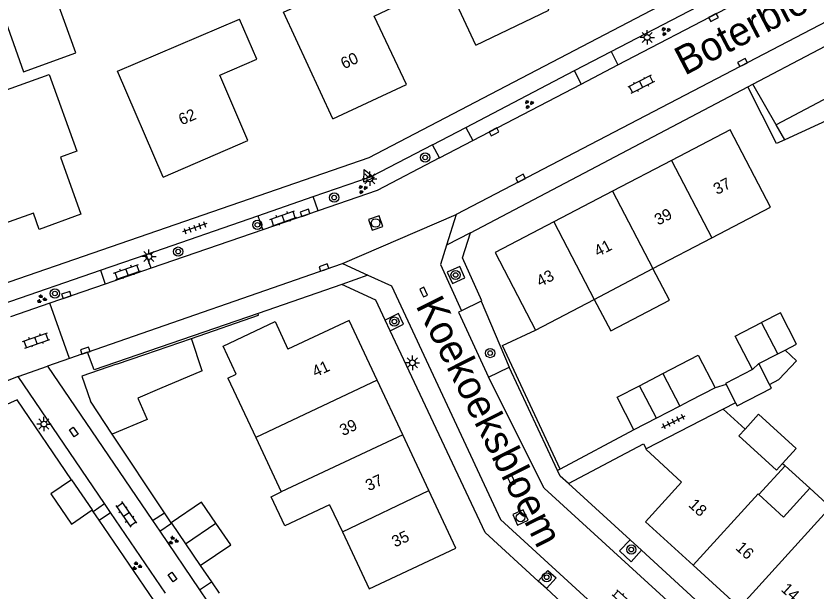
# Model space of a CAD drawing. Extents: x 136000 to 141014, y 402000 to 403500.
# Drawn here: x 137448.8 to 137518.5, y 402362.7 to 402412.9 of the extents above; entities that cross this region are included whole.
import ezdxf

# ---------------------------------------------------------------- set-up
doc = ezdxf.new("R2010")
doc.units = 0
for name, color, linetype in [('gg-afsc-erfafscheiding', 7, 'Continuous'), ('gg-afsc-muur', 7, 'Continuous'), ('gg-anno-huisnummerreeks BGT', 7, 'Continuous'), ('gg-anno-openbare ruimte label', 7, 'Continuous'), ('gg-bbg-bijgebouw', 7, 'Continuous'), ('gg-bbg-gedigitaliseerde bebouwing', 7, 'Continuous'), ('gg-bbg-gedigitaliseerde bijgebouw', 7, 'Continuous'), ('gg-bbg-hoofdgebouw', 7, 'Continuous'), ('gg-bbg-luifel en loopbrug', 7, 'Continuous'), ('gg-bbg-tussenscheiding', 7, 'Continuous'), ('gg-knt-verharding', 7, 'Continuous'), ('gg-knt-verharding nz', 7, 'Continuous'), ('gt-grn-groengrens', 7, 'Continuous'), ('gt-grn-weggrens', 7, 'Continuous'), ('gt-symb-boom', 7, 'Continuous'), ('gt-symb-groenvak', 7, 'Continuous'), ('gt-symb-klinker verharding', 7, 'Continuous'), ('gt-symb-kolk', 7, 'Continuous'), ('gt-symb-kolk center center', 7, 'Continuous'), ('gt-symb-lichtmast', 7, 'Continuous'), ('gt-symb-rioolschacht', 7, 'Continuous'), ('gt-symb-tegel verharding', 7, 'Continuous'), ('gt-symb-waterafsluiter', 7, 'Continuous')]:
    doc.layers.add(name, color=color, linetype=linetype)

# ---------------------------------------------------------------- blocks, each defined once
blk = doc.blocks.new('gt0-TEG1')
at = {"layer": 'gt-symb-tegel verharding'}
for p, q in [((-1.125, 0), (1.125, 0)), ((-0.9, -0.25), (-0.9, 0.25)), ((-0.45, -0.25), (-0.45, 0.25)), ((0, -0.25), (0, 0.25)), ((0.45, -0.25), (0.45, 0.25)), ((0.9, -0.25), (0.9, 0.25))]:
    blk.add_line(p, q, dxfattribs=at)
blk = doc.blocks.new('gt0-RS')
at = {"layer": 'gt-symb-rioolschacht'}
blk.add_lwpolyline([(-0.5, -0.5), (0.5, -0.5), (0.5, 0.5), (-0.5, 0.5)], close=True, dxfattribs=at)
blk.add_circle((0, 0), 0.375, dxfattribs=at)
blk = doc.blocks.new('gt0-BOOM')
at = {"layer": 'gt-symb-boom'}
for radius in [0.4, 0.2]:
    blk.add_circle((0, 0), radius, dxfattribs=at)
blk = doc.blocks.new('gt0-KL1')
at = {"layer": 'gt-symb-klinker verharding'}
for p, q in [((-1.15, 0.3), (1.15, 0.3)), ((-1, -0.3), (-1, 0.3)), ((-0.5, 0.3), (-0.5, 0.45)), ((0, -0.3), (0, 0.3)), ((0.5, 0.3), (0.5, 0.45)), ((1, -0.3), (1, 0.3)), ((-1.15, -0.3), (1.15, -0.3)), ((-0.5, -0.45), (-0.5, -0.3)), ((0.5, -0.45), (0.5, -0.3))]:
    blk.add_line(p, q, dxfattribs=at)
blk = doc.blocks.new('gt0-LMAST')
at = {"layer": 'gt-symb-lichtmast'}
for p, q in [((-0.182, 0.173), (-0.447, 0.438)), ((-0.005, 0.246), (-0.005, 0.621)), ((0.172, 0.173), (0.437, 0.438)), ((-0.255, -0.004), (-0.63, -0.004)), ((-0.182, -0.181), (-0.447, -0.446)), ((-0.005, -0.254), (-0.005, -0.629)), ((0.437, -0.446), (0.172, -0.181)), ((0.245, -0.004), (0.62, -0.004))]:
    blk.add_line(p, q, dxfattribs=at)
blk.add_circle((-0.005, -0.004), 0.25, dxfattribs=at)
blk = doc.blocks.new('gt0-KOLK')
at = {"layer": 'gt-symb-kolk'}
blk.add_lwpolyline([(0, 0), (0.375, 0), (0.375, 0.4), (-0.375, 0.4), (-0.375, 0), (0, 0)], dxfattribs=at)
blk = doc.blocks.new('gt0-GRVAK')
at = {"layer": 'gt-symb-groenvak'}
for p, q in [((-0.11, 0.189), (-0.228, 0.24)), ((-0.182, 0.153), (0.088, 0.153)), ((-0.091, 0.211), (-0.156, 0.322)), ((-0.047, 0.214), (-0.047, 0.393)), ((-0.004, 0.211), (0.061, 0.322)), ((0.015, 0.189), (0.133, 0.24)), ((0.262, -0.052), (0.197, 0.059)), ((0.305, -0.049), (0.305, 0.13)), ((0.349, -0.052), (0.414, 0.059)), ((-0.245, -0.228), (-0.363, -0.177)), ((-0.318, -0.264), (-0.047, -0.264)), ((-0.226, -0.206), (-0.291, -0.095)), ((-0.183, -0.203), (-0.183, -0.024)), ((-0.139, -0.206), (-0.074, -0.095)), ((-0.12, -0.228), (-0.002, -0.177)), ((0.243, -0.074), (0.125, -0.023)), ((0.17, -0.11), (0.441, -0.11)), ((0.368, -0.074), (0.486, -0.023))]:
    blk.add_line(p, q, dxfattribs=at)
blk = doc.blocks.new('gt0-KOLKCC')
at = {"layer": 'gt-symb-kolk center center'}
blk.add_lwpolyline([(-0.375, 0.2), (0.375, 0.2), (0.375, -0.2), (-0.375, -0.2)], close=True, dxfattribs=at)
blk = doc.blocks.new('gt0-WAFSL')
at = {"layer": 'gt-symb-waterafsluiter'}
for p, q in [((-0.5, -0.333), (0, 0.667)), ((0, 0.667), (0.5, -0.333)), ((0.5, -0.333), (-0.5, -0.333))]:
    blk.add_line(p, q, dxfattribs=at)

msp = doc.modelspace()

# ---------------------------------------------------------------- linework, layer by layer
at = {"layer": 'gg-afsc-erfafscheiding'}
for p, q in [((137515.072, 402401.775), (137512.57, 402406.716)), ((137489.352, 402388.066), (137491.8, 402382.31)), ((137510.678, 402380.806), (137509.722, 402380.528)), ((137511.515, 402379.204), (137510.431, 402378.673)), ((137502.659, 402376.851), (137496.223, 402373.433)), ((137461.776, 402369.648), (137457.231, 402376.485)), ((137455.568, 402369.76), (137455.48, 402369.89)), ((137456.088, 402368.998), (137455.568, 402369.76)), ((137462.367, 402368.76), (137461.776, 402369.648)), ((137460.879, 402361.969), (137456.088, 402368.998)), ((137464.899, 402365.048), (137465.873, 402363.621)), ((137465.873, 402363.621), (137466.535, 402362.651))]:
    msp.add_line(p, q, dxfattribs=at)
for points in [[(137496.223, 402373.433), (137491.2, 402384.192), (137494.088, 402385.525)], [(137453.69, 402372.52), (137448.936, 402379.473), (137446.85, 402378.54)]]:
    msp.add_lwpolyline(points, dxfattribs=at)
at = {"layer": 'gg-afsc-muur'}
for p, q in [((137524.471, 402406.085), (137515.799, 402402.108)), ((137515.799, 402402.108), (137515.072, 402401.775)), ((137464.116, 402384.817), (137469.976, 402386.835))]:
    msp.add_line(p, q, dxfattribs=at)
at = {"layer": 'gg-bbg-bijgebouw'}
for p, q in [((137503.141, 402380.704), (137505.172, 402381.757)), ((137505.172, 402381.757), (137506.644, 402378.916)), ((137510.639, 402380.88), (137510.678, 402380.806)), ((137510.678, 402380.806), (137511.515, 402379.204)), ((137506.644, 402378.916), (137504.635, 402377.875)), ((137504.635, 402377.875), (137502.659, 402376.851)), ((137453.69, 402372.52), (137455.48, 402369.89)), ((137462.367, 402368.76), (137462.394, 402368.721)), ((137462.394, 402368.721), (137463.608, 402366.94)), ((137463.608, 402366.94), (137464.899, 402365.048))]:
    msp.add_line(p, q, dxfattribs=at)
for points in [[(137451.97, 402415.48), (137447.4, 402413.85), (137449.49, 402408.04), (137454.05, 402409.68), (137451.97, 402415.48)], [(137502.659, 402376.851), (137501.187, 402379.692), (137503.141, 402380.704)], [(137453.69, 402372.52), (137451.87, 402371.28), (137453.67, 402368.65), (137455.48, 402369.89)], [(137466.259, 402368.733), (137465.011, 402370.563), (137462.367, 402368.76)], [(137464.899, 402365.048), (137467.543, 402366.851), (137466.259, 402368.733)]]:
    msp.add_lwpolyline(points, dxfattribs=at)
at = {"layer": 'gg-bbg-gedigitaliseerde bebouwing'}
for p, q in [((137504.314, 402390.891), (137509.429, 402393.57)), ((137499.199, 402388.211), (137504.314, 402390.891)), ((137494.1, 402385.54), (137499.199, 402388.211)), ((137467.299, 402381.352), (137469.728, 402376.185)), ((137510.431, 402378.673), (137512.345, 402376.927)), ((137469.728, 402376.185), (137471.952, 402371.452)), ((137515.831, 402373.73), (137513.538, 402371.22)), ((137515.61, 402373.932), (137515.751, 402373.803)), ((137515.751, 402373.803), (137515.831, 402373.73)), ((137517.98, 402371.78), (137519.788, 402370.128)), ((137476.154, 402370.34), (137477.268, 402367.973))]:
    msp.add_line(p, q, dxfattribs=at)
for points in [[(137488.88, 402410.35), (137484.535, 402419.701), (137488.172, 402421.343)], [(137476.45, 402403.93), (137472.144, 402413.228), (137475.57, 402414.798)], [(137461.66, 402398.85), (137457.695, 402408.077), (137468.31, 402412.62)], [(137509.429, 402393.57), (137514.548, 402396.252), (137511.05, 402402.97)], [(137512.345, 402376.927), (137511.806, 402376.336), (137515.077, 402373.349), (137515.61, 402373.932)], [(137476.154, 402370.34), (137472.261, 402368.51), (137471.072, 402371.039), (137471.952, 402371.452)], [(137513.538, 402371.22), (137515.679, 402369.263), (137517.98, 402371.78)], [(137477.268, 402367.973), (137479.601, 402363.016), (137487.15, 402366.56)]]:
    msp.add_lwpolyline(points, dxfattribs=at)
at = {"layer": 'gg-bbg-gedigitaliseerde bijgebouw'}
for p, q in [((137460.068, 402383.423), (137464.116, 402384.817)), ((137465.063, 402381.989), (137464.116, 402384.817)), ((137515.176, 402383.472), (137515.818, 402383.802)), ((137457.59, 402382.57), (137460.068, 402383.423)), ((137465.063, 402381.989), (137461.336, 402380.417)), ((137512.976, 402382.1), (137510.639, 402380.88)), ((137457.231, 402376.485), (137455.32, 402379.36))]:
    msp.add_line(p, q, dxfattribs=at)
for points in [[(137515.818, 402383.802), (137516.826, 402384.32), (137515.426, 402387.046), (137513.775, 402386.198)], [(137512.976, 402382.1), (137511.478, 402385.017), (137513.775, 402386.198)], [(137514.462, 402380.801), (137515.279, 402381.229), (137516.816, 402382.863), (137515.818, 402383.802)], [(137457.59, 402382.57), (137454.57, 402381.53), (137455.32, 402379.36)], [(137461.336, 402380.417), (137459.467, 402379.629), (137460.255, 402377.761), (137457.231, 402376.485)], [(137511.515, 402379.204), (137511.645, 402378.95), (137514.626, 402380.482), (137514.462, 402380.801)]]:
    msp.add_lwpolyline(points, dxfattribs=at)
at = {"layer": 'gg-bbg-hoofdgebouw'}
for p, q in [((137511.05, 402402.97), (137505.927, 402400.305)), ((137505.927, 402400.305), (137500.804, 402397.64)), ((137500.804, 402397.64), (137495.681, 402394.974)), ((137467.299, 402381.352), (137468.032, 402381.697)), ((137482.534, 402376.423), (137480.312, 402381.173)), ((137510.431, 402378.673), (137503.71, 402375.196)), ((137484.801, 402371.58), (137482.534, 402376.423)), ((137487.15, 402366.56), (137484.801, 402371.58)), ((137511.845, 402361.394), (137507.811, 402365.074))]:
    msp.add_line(p, q, dxfattribs=at)
for points in [[(137488.88, 402410.35), (137495.25, 402413.4), (137492.39, 402419.36), (137495.11, 402420.64)], [(137476.45, 402403.93), (137482.84, 402406.91), (137480.05, 402412.87), (137482.75, 402414.14)], [(137461.66, 402398.85), (137469.05, 402402.04), (137466.6, 402407.73), (137469.83, 402409.14), (137468.31, 402412.62)], [(137454.13, 402401.12), (137452.71, 402400.61), (137454.5, 402395.64), (137450.86, 402394.31), (137450.36, 402395.72), (137446.52, 402394.35), (137442.81, 402404.59), (137451.73, 402407.8), (137454.13, 402401.12)], [(137495.681, 402394.974), (137490.56, 402392.31), (137494.1, 402385.54)], [(137468.032, 402381.697), (137466.879, 402384.149), (137471.403, 402386.277), (137472.531, 402383.879)], [(137480.312, 402381.173), (137477.87, 402386.39), (137472.531, 402383.879)], [(137506.81, 402372.31), (137503.683, 402375.182), (137503.71, 402375.196)], [(137507.811, 402365.074), (137503.66, 402368.86), (137506.81, 402372.31)]]:
    msp.add_lwpolyline(points, dxfattribs=at)
at = {"layer": 'gg-bbg-luifel en loopbrug'}
for p, q in [((137509.722, 402380.528), (137507.524, 402379.384)), ((137507.524, 402379.384), (137506.644, 402378.916)), ((137517.98, 402371.78), (137515.831, 402373.73))]:
    msp.add_line(p, q, dxfattribs=at)
for points in [[(137499.199, 402388.211), (137500.635, 402385.471), (137505.75, 402388.151), (137504.314, 402390.891)], [(137505.172, 402381.757), (137508.24, 402383.348), (137509.722, 402380.528)], [(137512.345, 402376.927), (137513.518, 402378.213), (137516.791, 402375.227), (137515.61, 402373.932)]]:
    msp.add_lwpolyline(points, dxfattribs=at)
at = {"layer": 'gg-bbg-tussenscheiding'}
for p, q in [((137505.927, 402400.305), (137509.429, 402393.57)), ((137500.804, 402397.64), (137504.314, 402390.891)), ((137495.681, 402394.974), (137499.199, 402388.211)), ((137515.176, 402383.472), (137513.775, 402386.198)), ((137513.526, 402382.624), (137515.176, 402383.472)), ((137513.526, 402382.624), (137512.976, 402382.1)), ((137514.462, 402380.801), (137513.526, 402382.624)), ((137480.312, 402381.173), (137469.728, 402376.185)), ((137504.635, 402377.875), (137503.141, 402380.704)), ((137482.534, 402376.423), (137471.952, 402371.452)), ((137477.268, 402367.973), (137484.801, 402371.58)), ((137519.788, 402370.128), (137511.845, 402361.394)), ((137463.608, 402366.94), (137466.259, 402368.733))]:
    msp.add_line(p, q, dxfattribs=at)
msp.add_lwpolyline([(137513.538, 402371.22), (137513.463, 402371.288), (137507.811, 402365.074)], dxfattribs=at)
at = {"layer": 'gg-knt-verharding'}
for p, q in [((137500.677, 402409.798), (137510.181, 402414.753)), ((137501.254, 402408.621), (137510.752, 402413.574)), ((137497.477, 402408.129), (137500.677, 402409.798)), ((137500.677, 402409.798), (137501.254, 402408.621)), ((137526.718, 402409.6), (137515.045, 402403.426)), ((137488.015, 402403.194), (137497.477, 402408.129)), ((137498.073, 402406.962), (137497.477, 402408.129)), ((137488.617, 402402.051), (137498.073, 402406.962)), ((137512.57, 402406.716), (137513.025, 402406.956)), ((137515.045, 402403.426), (137513.025, 402406.956)), ((137488.44, 402394.02), (137512.57, 402406.716)), ((137485.11, 402401.679), (137488.015, 402403.194)), ((137488.015, 402403.194), (137488.617, 402402.051)), ((137485.11, 402401.679), (137479.812, 402398.917)), ((137485.741, 402400.534), (137485.11, 402401.679)), ((137474.722, 402397.16), (137479.812, 402398.917)), ((137469.918, 402395.495), (137474.722, 402397.16)), ((137475.149, 402395.924), (137474.722, 402397.16)), ((137475.149, 402395.924), (137470.343, 402394.268)), ((137460.174, 402392.125), (137469.918, 402395.495)), ((137469.918, 402395.495), (137470.343, 402394.268)), ((137470.343, 402394.268), (137460.627, 402390.925)), ((137456.208, 402390.754), (137460.174, 402392.125)), ((137460.627, 402390.925), (137460.174, 402392.125)), ((137460.627, 402390.925), (137456.613, 402389.544)), ((137447.632, 402387.787), (137456.208, 402390.754)), ((137456.208, 402390.754), (137456.613, 402389.544)), ((137456.613, 402389.544), (137451.785, 402387.882)), ((137477.23, 402389.51), (137469.921, 402386.994)), ((137489.352, 402388.066), (137487.63, 402387.21)), ((137451.785, 402387.882), (137448.363, 402386.704)), ((137453.495, 402383.066), (137451.785, 402387.882)), ((137481.438, 402385.464), (137480.996, 402386.405)), ((137455.06, 402383.61), (137453.495, 402383.066)), ((137453.495, 402383.066), (137451.58, 402382.4)), ((137449.03, 402381.51), (137451.58, 402382.4)), ((137451.58, 402382.4), (137460.732, 402368.954)), ((137490, 402381.44), (137491.8, 402382.31)), ((137496.011, 402373.318), (137491.8, 402382.31)), ((137449.03, 402381.51), (137447.317, 402380.834)), ((137456.565, 402370.439), (137449.03, 402381.51)), ((137496.223, 402373.433), (137496.011, 402373.318)), ((137502.322, 402367.283), (137496.959, 402372.183)), ((137455.568, 402369.76), (137456.565, 402370.439)), ((137457.084, 402369.677), (137456.565, 402370.439)), ((137456.088, 402368.998), (137457.084, 402369.677)), ((137461.87, 402362.644), (137457.084, 402369.677)), ((137460.732, 402368.954), (137461.776, 402369.648)), ((137460.732, 402368.954), (137461.36, 402368.032)), ((137461.36, 402368.032), (137462.394, 402368.721)), ((137461.36, 402368.032), (137464.841, 402362.917)), ((137503.317, 402366.375), (137502.322, 402367.283)), ((137515.863, 402354.913), (137503.317, 402366.375)), ((137464.841, 402362.917), (137465.873, 402363.621)), ((137495.035, 402363.038), (137494.313, 402363.697)), ((137464.841, 402362.917), (137465.502, 402361.946)), ((137506.174, 402352.862), (137495.035, 402363.038))]:
    msp.add_line(p, q, dxfattribs=at)
for points in [[(137529.46, 402422.83), (137528.05, 402424.26), (137524.01, 402423.76), (137479.57, 402400.54), (137447.456, 402389.458)], [(137485.741, 402400.534), (137480.31, 402397.7), (137475.149, 402395.924)], [(137489.352, 402388.066), (137489.4, 402388.09), (137487.72, 402391.84), (137488.44, 402394.02)], [(137486.393, 402390.599), (137486.845, 402389.612), (137487.941, 402390.099), (137487.489, 402391.086), (137486.393, 402390.599)], [(137480.996, 402386.405), (137480.17, 402388.16), (137477.23, 402389.51)], [(137469.921, 402386.994), (137455.65, 402382.08), (137455.06, 402383.61)], [(137481.438, 402385.464), (137482.588, 402386.061), (137482.144, 402386.991), (137480.996, 402386.405)], [(137487.63, 402387.21), (137487.38, 402387.1), (137490, 402381.44)], [(137494.313, 402363.697), (137489.69, 402367.92), (137481.438, 402385.464)], [(137496.959, 402372.183), (137503.484, 402375.633), (137503.71, 402375.196)], [(137496.959, 402372.183), (137496.24, 402372.83), (137496.011, 402373.318)], [(137502.322, 402367.283), (137501.414, 402366.318), (137502.405, 402365.371), (137503.317, 402366.375)], [(137494.313, 402363.697), (137495.152, 402364.616), (137495.873, 402363.961), (137495.035, 402363.038)]]:
    msp.add_lwpolyline(points, dxfattribs=at)
at = {"layer": 'gg-knt-verharding nz'}
for p, q in [((137523.588, 402414.575), (137487.19, 402395.6)), ((137487.19, 402395.6), (137486.338, 402392.933)), ((137455.06, 402383.61), (137477.27, 402391.33)), ((137477.27, 402391.33), (137479.5, 402390.322))]:
    msp.add_line(p, q, dxfattribs=at)
for points in [[(137513.025, 402406.956), (137523.41, 402412.42), (137525.208, 402412.498)], [(137486.338, 402392.933), (137485.8, 402391.25), (137487.63, 402387.21)], [(137479.5, 402390.322), (137481.54, 402389.4), (137491.03, 402369.04), (137528.618, 402334.631)], [(137531.38, 402338.41), (137494.85, 402371.78), (137490, 402381.44)]]:
    msp.add_lwpolyline(points, dxfattribs=at)
at = {"layer": 'gt-grn-groengrens'}
for p, q in [((137515.799, 402402.108), (137515.045, 402403.426)), ((137469.976, 402386.835), (137469.921, 402386.994))]:
    msp.add_line(p, q, dxfattribs=at)
at = {"layer": 'gt-grn-weggrens'}
for p, q in [((137498.073, 402406.962), (137501.254, 402408.621)), ((137485.741, 402400.534), (137488.617, 402402.051)), ((137477.27, 402391.33), (137487.19, 402395.6)), ((137488.44, 402394.02), (137486.338, 402392.933)), ((137479.5, 402390.322), (137477.23, 402389.51))]:
    msp.add_line(p, q, dxfattribs=at)

# ---------------------------------------------------------------- block references
at = {"layer": 'gt-symb-boom'}
for p in [(137484.479, 402400.568), (137476.558, 402397.08), (137469.867, 402394.709), (137462.968, 402392.377), (137487.126, 402390.339), (137452.233, 402388.726), (137481.8, 402386.284), (137490.135, 402383.54), (137502.428, 402366.436), (137495.058, 402364.024)]:
    msp.add_blockref('gt0-BOOM', p, dxfattribs=at)
at = {"layer": 'gt-symb-groenvak', "rotation": 27.513061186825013}
for p in [(137505.397, 402411.558), (137493.49, 402405.214), (137479.008, 402397.81)]:
    msp.add_blockref('gt0-GRVAK', p, dxfattribs=at)
at = {"layer": 'gt-symb-groenvak'}
for p in [(137451.064, 402388.251), (137462.533, 402367.227), (137459.358, 402365.001)]:
    msp.add_blockref('gt0-GRVAK', p, dxfattribs=at)
at = {"layer": 'gt-symb-klinker verharding'}
for p, rotation in [((137503.275, 402406.938), -152.999345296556), ((137472.126, 402395.264), 19.3224823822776), ((137458.523, 402390.599), 19.322482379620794), ((137450.598, 402384.633), 19.322482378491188), ((137458.452, 402369.502), -55.308471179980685), ((137501.826, 402361.95), 138.0000087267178)]:
    msp.add_blockref('gt0-KL1', p, dxfattribs=dict(at, rotation=rotation))
at = {"layer": 'gt-symb-kolk'}
for p, rotation in [((137509.68, 402412.572), 27.513061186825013), ((137512.204, 402408.649), 27.513061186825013), ((137490.562, 402402.615), 27.513061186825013), ((137492.879, 402398.576), 27.513061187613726), ((137474.082, 402395.559), 18.96025108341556), ((137475.728, 402390.796), 19.214311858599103), ((137453.308, 402388.406), 19.08724450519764), ((137484.166, 402388.773), -65.61293328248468), ((137454.938, 402383.568), 19.26841496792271), ((137491.817, 402372.374), -65.61293328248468)]:
    msp.add_blockref('gt0-KOLK', p, dxfattribs=dict(at, rotation=rotation))
at = {"layer": 'gt-symb-kolk center center', "rotation": 124.99730920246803}
for p in [(137453.875, 402376.675), (137462.476, 402364.049)]:
    msp.add_blockref('gt0-KOLKCC', p, dxfattribs=at)
at = {"layer": 'gt-symb-lichtmast'}
for p in [(137503.818, 402411.025), (137479.657, 402398.717), (137460.425, 402391.95), (137483.368, 402382.696), (137451.282, 402377.366)]:
    msp.add_blockref('gt0-LMAST', p, dxfattribs=at)
at = {"layer": 'gt-symb-rioolschacht'}
for p, rotation in [((137480.165, 402394.866), 18.96025108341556), ((137492.777, 402369.232), -65.61293328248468)]:
    msp.add_blockref('gt0-RS', p, dxfattribs=dict(at, rotation=rotation))
at = {"layer": 'gt-symb-tegel verharding'}
for p, rotation in [((137464.417, 402394.454), -160.73158503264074), ((137506.106, 402377.57), 26.590652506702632)]:
    msp.add_blockref('gt0-TEG1', p, dxfattribs=dict(at, rotation=rotation))
at = {"layer": 'gt-symb-waterafsluiter', "rotation": 25.027278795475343}
msp.add_blockref('gt0-WAFSL', (137479.445, 402398.927), dxfattribs=at)

# ---------------------------------------------------------------- texts
at = {"layer": 'gg-anno-huisnummerreeks BGT'}
for s, rotation, p in [('60', 25, (137477.414, 402408.241)), ('62', 23.3, (137463.267, 402403.357)), ('37', 27.5, (137509.895, 402397.296)), ('39', 27.5, (137504.769, 402394.629)), ('41', 27.5, (137499.519, 402391.899)), ('43', 27.5, (137494.492, 402389.283)), ('41', 25.1, (137474.923, 402381.416)), ('39', 25.1, (137477.315, 402376.304)), ('37', 25.1, (137479.562, 402371.503)), ('18', 317.6, (137507.346, 402370.236)), ('35', 25.1, (137481.853, 402366.608)), ('16', 317.6, (137511.438, 402366.503)), ('14', 317.6, (137515.395, 402362.894))]:
    msp.add_text(s, height=1, rotation=rotation, dxfattribs=at).set_placement(p)
at = {"layer": 'gg-anno-openbare ruimte label'}
for s, rotation, p in [('Boterbloem', 27.6, (137507.075, 402407.671)), ('Koekoeksbloem', 296.7, (137483.614, 402387.68))]:
    msp.add_text(s, height=2.5, rotation=rotation, dxfattribs=at).set_placement(p)

doc.saveas('drawing.dxf')
